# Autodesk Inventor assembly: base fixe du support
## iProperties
Shininess: 41.0
Length Units: 11269
Angle Units: 11279
Time Units: 11290
Mass Units: 11283
Length Display Precision: 3
Angle Display Precision: 2
Created: 2002-05
Part Number: base fixe du support
Document SubType Name: Assemblage
Designer: REVEST Pierre
Density: 0.0
Volumn: 0.0
Area: 0.0
PropertySet Name: Model Information
Control State: 0
Master: False
Checked Out: False
Author: REVEST Pierre
